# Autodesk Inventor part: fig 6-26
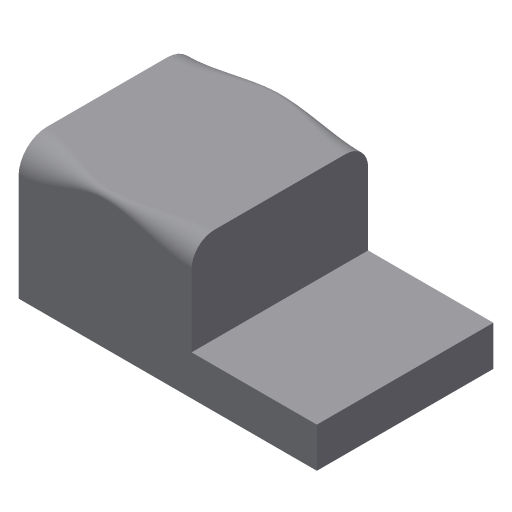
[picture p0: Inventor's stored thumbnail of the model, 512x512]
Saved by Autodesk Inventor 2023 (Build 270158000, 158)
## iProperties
Created: 2004-05
Part Number: fig 6-26
Document SubType Name: Modeling
Designer: CADCIM Technologies
Manufacturer: Standard
Standards Organization: Custom
Density: 1 g/cm^3
Material: Generic
Appearance: Default
Author: CADCIM Technologies
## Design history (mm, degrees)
node "Sketch1"
sketch "Sketch2"
  geometry: L1 (0.098, 47.711)-(0.098, 0.049); L2 (0.098, 0.049)-(-105.483, 0.049); L3 (-105.483, 0.049)-(-105.483, 14.192); L4 (-105.483, 14.192)-(-61.139, 14.192); L5 (-61.139, 14.192)-(-61.139, 47.711); L6 (-61.139, 47.711)-(0.098, 47.711)
  constraints: 12 end point, 3 parallel, 2 perpendicular, 1 vertical
extrude "Extrusion1" new body sketch "Sketch2" stored distance "d0" = 62.5; taper "d1" = 0 deg
fillet "Fillet9" dims "d61" = 10, "d62" = 8, "d63" = 2, "d64" = 5
fillet "Fillet10" dims "d65" = 8, "d66" = 10, "d67" = 2, "d68" = 5
body "Solid1"
